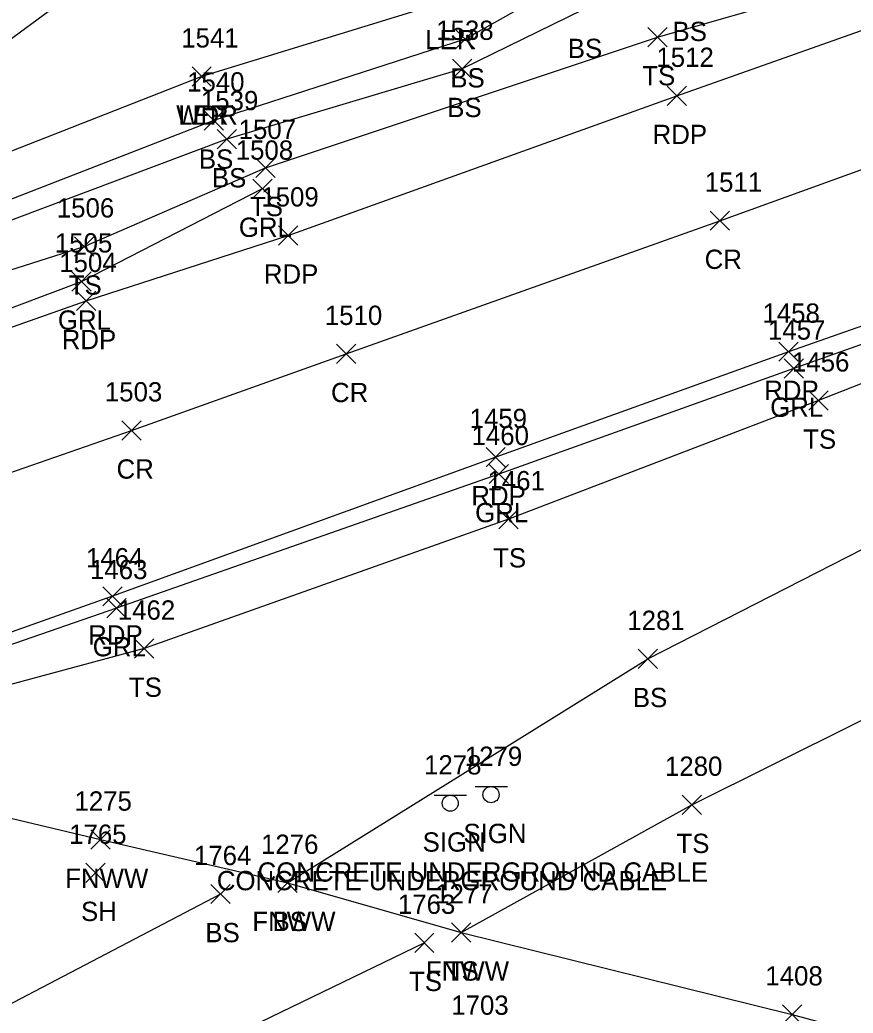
# Model space of a CAD drawing. Extents: x 1599569 to 1610055, y 642560 to 647860.
# Drawn here: x 1601829.7 to 1601916, y 647289.9 to 647392.8 of the extents above; entities that cross this region are included whole.
import ezdxf

# ---------------------------------------------------------------- set-up
doc = ezdxf.new("R2010")
doc.units = 0
for name, color, linetype in [('L_A', 7, 'Continuous'), ('L_I', 7, 'Continuous'), ('L_TIC', 7, 'Continuous'), ('LARO', 7, 'Continuous'), ('LAWA', 7, 'Continuous'), ('LELB', 7, 'Continuous'), ('LFNC', 7, 'Continuous'), ('P_A', 7, 'Continuous'), ('P_I', 7, 'Continuous'), ('P_TIC', 7, 'Continuous'), ('PET', 7, 'Continuous'), ('PRC', 7, 'Continuous'), ('R_A', 7, 'Continuous'), ('R_I', 7, 'Continuous'), ('R_TIC', 7, 'Continuous'), ('RGR', 7, 'Continuous'), ('S_A', 7, 'Continuous'), ('S_C', 7, 'Continuous'), ('S_I', 7, 'Continuous'), ('SSGN', 7, 'Continuous')]:
    doc.layers.add(name, color=color, linetype=linetype)

msp = doc.modelspace()

# ---------------------------------------------------------------- linework, layer by layer
at = {"layer": 'L_TIC'}
for points in [[(1601894.73, 647390.04), (1601896.73, 647392.04)], [(1601896.73, 647390.04), (1601894.73, 647392.04)], [(1601874.8, 647389.82), (1601876.8, 647391.82)], [(1601876.8, 647389.82), (1601874.8, 647391.82)], [(1601847.49, 647385.96), (1601849.49, 647387.96)], [(1601849.49, 647385.96), (1601847.49, 647387.96)], [(1601847.49, 647385.96), (1601849.49, 647387.96)], [(1601849.49, 647385.96), (1601847.49, 647387.96)], [(1601874.49, 647386.75), (1601876.49, 647388.75)], [(1601876.49, 647386.75), (1601874.49, 647388.75)], [(1601848.76, 647381.4), (1601850.76, 647383.4)], [(1601850.76, 647381.4), (1601848.76, 647383.4)], [(1601850.11, 647379.46), (1601852.11, 647381.46)], [(1601852.11, 647379.46), (1601850.11, 647381.46)], [(1601854.09, 647376.48), (1601856.09, 647378.48)], [(1601856.09, 647376.48), (1601854.09, 647378.48)], [(1601835.31, 647368.34), (1601837.31, 647370.34)], [(1601837.31, 647368.34), (1601835.31, 647370.34)], [(1601911.4, 647352.37), (1601913.4, 647354.37)], [(1601913.4, 647352.37), (1601911.4, 647354.37)], [(1601879.28, 647340.06), (1601881.28, 647342.06)], [(1601881.28, 647340.06), (1601879.28, 647342.06)], [(1601841.54, 647326.65), (1601843.54, 647328.65)], [(1601843.54, 647326.65), (1601841.54, 647328.65)], [(1601893.72, 647325.58), (1601895.72, 647327.58)], [(1601895.72, 647325.58), (1601893.72, 647327.58)], [(1601898.27, 647310.46), (1601900.27, 647312.46)], [(1601900.27, 647310.46), (1601898.27, 647312.46)], [(1601837.01, 647306.85), (1601839.01, 647308.85)], [(1601839.01, 647306.85), (1601837.01, 647308.85)], [(1601836.5, 647303.41), (1601838.5, 647305.41)], [(1601838.5, 647303.41), (1601836.5, 647305.41)], [(1601856.39, 647302.37), (1601858.39, 647304.37)], [(1601858.39, 647302.37), (1601856.39, 647304.37)], [(1601856.39, 647302.37), (1601858.39, 647304.37)], [(1601858.39, 647302.37), (1601856.39, 647304.37)], [(1601849.43, 647301.21), (1601851.43, 647303.21)], [(1601851.43, 647301.21), (1601849.43, 647303.21)], [(1601874.37, 647297.23), (1601876.37, 647299.23)], [(1601876.37, 647297.23), (1601874.37, 647299.23)], [(1601874.37, 647297.23), (1601876.37, 647299.23)], [(1601876.37, 647297.23), (1601874.37, 647299.23)], [(1601870.56, 647296.15), (1601872.56, 647298.15)], [(1601872.56, 647296.15), (1601870.56, 647298.15)], [(1601908.67, 647288.73), (1601910.67, 647290.73)], [(1601910.67, 647288.73), (1601908.67, 647290.73)]]:
    msp.add_lwpolyline(points, dxfattribs=at)
at = {"layer": 'LARO'}
msp.add_lwpolyline([(1602281.17, 647528.1), (1602249.28, 647518.68), (1602215.29, 647506.81), (1602182.96, 647503.09), (1602138.81, 647485.94), (1602110.91, 647474.13), (1602102.89, 647472.66), (1602065.84, 647459), (1602030.57, 647446.06), (1601996.63, 647434.93), (1601966.44, 647449.06), (1601954.75, 647432.61), (1601939.14, 647421.32), (1601907.5, 647403.47), (1601898.14, 647399.78), (1601888.11, 647399.67), (1601874.07, 647394.79), (1601848.49, 647386.96)], dxfattribs=at)
at = {"layer": 'LAWA'}
msp.add_lwpolyline([(1601848.49, 647386.96), (1601821.55, 647376.37), (1601804, 647372.6), (1601777.94, 647362.34), (1601760.01, 647349.17), (1601740.19, 647347.52), (1601705.98, 647345.02), (1601664.4, 647344.49), (1601627.88, 647353.13)], dxfattribs=at)
at = {"layer": 'LELB'}
for points in [[(1602281.75, 647527.04), (1602249.8, 647516.84), (1602215.67, 647505.92), (1602184.38, 647497.32), (1602140.31, 647484.48), (1602111.03, 647472.46), (1602103.56, 647472.02), (1602066.93, 647456.96), (1602030.71, 647444.95), (1601997.32, 647432.85), (1601974.14, 647429.14), (1601941.15, 647416.78), (1601908.35, 647402.2), (1601898.71, 647398.5), (1601889.19, 647398.4), (1601875.8, 647390.82), (1601849.76, 647382.4), (1601821.01, 647371.25), (1601793.34, 647364.77), (1601777.94, 647362.34), (1601752.2, 647359.53), (1601736.48, 647357.95), (1601705.98, 647345.02)], [(1602280.55, 647523.47), (1602249.62, 647512.84), (1602216.53, 647503.11), (1602185.17, 647491.71), (1602142.18, 647479.3), (1602111.48, 647470.2), (1602106.19, 647468.46), (1602102.05, 647467.18), (1602101.62, 647468.1), (1602067.36, 647454.23), (1602033.18, 647442.57), (1601998.29, 647429.71), (1601975.48, 647422.42), (1601942.86, 647410.81), (1601909.09, 647400.02), (1601898.83, 647395.63), (1601887.98, 647393.87), (1601875.49, 647387.75), (1601851.11, 647380.46), (1601821.5, 647369.32), (1601787.55, 647360.24), (1601760.01, 647349.17)], [(1601875.37, 647298.23), (1601899.27, 647311.46), (1601933.4, 647328.44), (1601966.96, 647349.6), (1601991.6, 647361.72), (1602007.33, 647369.55), (1602053.05, 647388.73), (1602108.48, 647405.48), (1602138.7, 647415.54), (1602162.27, 647422.58), (1602191.63, 647430.16), (1602222.72, 647436.69), (1602253.77, 647437.09), (1602274.71, 647434), (1602308.64, 647432.46), (1602335.54, 647436.29), (1602372.31, 647451.76), (1602413.17, 647464.59), (1602450.85, 647476.95), (1602485.79, 647485.59)], [(1602272.83, 647479.89), (1602236.83, 647468.86), (1602208.71, 647455.65), (1602173.71, 647445.42), (1602136.85, 647432.86), (1602103.5, 647421.49), (1602068.54, 647408.84), (1602020.23, 647391.97), (1601979.79, 647378.49), (1601945.53, 647366.37), (1601912.4, 647353.37), (1601880.28, 647341.06), (1601842.54, 647327.65), (1601807.18, 647318.11)], [(1601770.52, 647348.15), (1601798.65, 647357.36), (1601836.31, 647369.34), (1601855.09, 647377.48), (1601895.73, 647391.04), (1601936.03, 647402.6), (1601976.97, 647416.76)], [(1601850.43, 647302.21), (1601817.07, 647284.74), (1601803.58, 647280.33), (1601784.13, 647281.69), (1601758.75, 647290.86), (1601723.07, 647307), (1601685.47, 647323.96), (1601675.62, 647324.78), (1601658.01, 647334.35), (1601634.9, 647343.88), (1601612.64, 647349.36), (1601572.76, 647365.6), (1601544.62, 647379.24), (1601520.15, 647401.41)], [(1601857.39, 647303.37), (1601894.72, 647326.58), (1601931.36, 647345.31), (1601962.26, 647363.09), (1601988.12, 647373.2), (1602026.56, 647383.89)], [(1601871.56, 647297.15), (1601825.85, 647275.03), (1601803.11, 647261.21)]]:
    msp.add_lwpolyline(points, dxfattribs=at)
at = {"layer": 'LFNC'}
for points in [[(1601895.17, 647441.71), (1601881.57, 647431.46), (1601862.81, 647416.78), (1601844.07, 647402.17), (1601817.02, 647382.22)], [(1601805.75, 647315.97), (1601814.87, 647313.37), (1601838.01, 647307.85), (1601857.39, 647303.37), (1601875.37, 647298.23), (1601909.67, 647289.73), (1601944.01, 647280.41), (1601968.24, 647274.13), (1601982.37, 647269.76), (1602013.8, 647257.69), (1602065.95, 647235.95), (1602107.23, 647215.87), (1602133.46, 647203.49), (1602174.23, 647185.03), (1602218.38, 647164.67)]]:
    msp.add_lwpolyline(points, dxfattribs=at)
at = {"layer": 'P_TIC'}
for points in [[(1601896.73, 647383.95), (1601898.73, 647385.95)], [(1601898.73, 647383.95), (1601896.73, 647385.95)], [(1601901.17, 647371.01), (1601903.17, 647373.01)], [(1601903.17, 647371.01), (1601901.17, 647373.01)], [(1601856.45, 647369.48), (1601858.45, 647371.48)], [(1601858.45, 647369.48), (1601856.45, 647371.48)], [(1601835.51, 647362.69), (1601837.51, 647364.69)], [(1601837.51, 647362.69), (1601835.51, 647364.69)], [(1601862.46, 647357.2), (1601864.46, 647359.2)], [(1601864.46, 647357.2), (1601862.46, 647359.2)], [(1601908.28, 647357.43), (1601910.28, 647359.43)], [(1601910.28, 647357.43), (1601908.28, 647359.43)], [(1601840.23, 647349.27), (1601842.23, 647351.27)], [(1601842.23, 647349.27), (1601840.23, 647351.27)], [(1601877.95, 647346.51), (1601879.95, 647348.51)], [(1601879.95, 647346.51), (1601877.95, 647348.51)], [(1601838.24, 647332.07), (1601840.24, 647334.07)], [(1601840.24, 647332.07), (1601838.24, 647334.07)]]:
    msp.add_lwpolyline(points, dxfattribs=at)
at = {"layer": 'PET'}
msp.add_lwpolyline([(1601944.09, 647370.64), (1601909.28, 647358.43), (1601878.95, 647347.51), (1601839.24, 647333.07), (1601805.32, 647321.01), (1601803.15, 647319.96), (1601792.41, 647316.42), (1601770.61, 647326.17), (1601751.67, 647334.63), (1601759.02, 647336.99), (1601802.16, 647351.59), (1601836.51, 647363.69), (1601857.45, 647370.48), (1601897.73, 647384.95), (1601937.45, 647399.06)], dxfattribs=at)
at = {"layer": 'PRC'}
msp.add_lwpolyline([(1601770.61, 647326.17), (1601806.22, 647338.1), (1601841.23, 647350.27), (1601863.46, 647358.2), (1601902.17, 647372.01), (1601941.02, 647386.06), (1601983.17, 647400.81)], dxfattribs=at)
at = {"layer": 'R_TIC'}
for points in [[(1601853.79, 647374.33), (1601855.79, 647376.33)], [(1601855.79, 647374.33), (1601853.79, 647376.33)], [(1601835.05, 647364.71), (1601837.05, 647366.71)], [(1601837.05, 647364.71), (1601835.05, 647366.71)], [(1601908.85, 647355.68), (1601910.85, 647357.68)], [(1601910.85, 647355.68), (1601908.85, 647357.68)], [(1601878.27, 647344.75), (1601880.27, 647346.75)], [(1601880.27, 647344.75), (1601878.27, 647346.75)], [(1601838.66, 647330.85), (1601840.66, 647332.85)], [(1601840.66, 647330.85), (1601838.66, 647332.85)]]:
    msp.add_lwpolyline(points, dxfattribs=at)
at = {"layer": 'RGR'}
for points in [[(1602208.13, 647459.7), (1602171.04, 647448.96), (1602135.43, 647436.66), (1602102.2, 647424.86), (1602066.88, 647412.28), (1602018.59, 647395.18), (1601979.38, 647381.34), (1601944.8, 647369.09), (1601909.85, 647356.68), (1601879.27, 647345.75), (1601839.66, 647331.85), (1601805.55, 647320.04)], [(1601760.15, 647338.14), (1601801.96, 647352.88), (1601836.05, 647365.71), (1601854.79, 647375.33)]]:
    msp.add_lwpolyline(points, dxfattribs=at)
at = {"layer": 'SSGN'}
for p, q in [((1601876.82, 647313.34), (1601880.16, 647313.34)), ((1601872.59, 647312.45), (1601875.93, 647312.45)), ((1601878.47, 647312.51), (1601878.47, 647312.51)), ((1601874.24, 647311.62), (1601874.24, 647311.62))]:
    msp.add_line(p, q, dxfattribs=at)
for centre in [(1601878.47, 647312.51), (1601874.24, 647311.62)]:
    msp.add_circle(centre, 0.833, dxfattribs=at)

# ---------------------------------------------------------------- texts
at = {"layer": 'L_A'}
for s, p in [('BS', (1601897.27, 647390.63)), ('LER', (1601871.65, 647389.79)), ('BS', (1601886.42, 647388.87)), ('TS', (1601894.14, 647386.04)), ('BS', (1601874.25, 647385.82)), ('WDR', (1601845.85, 647381.96)), ('LER', (1601846.07, 647381.96)), ('BS', (1601873.93, 647382.75)), ('BS', (1601848.2, 647377.4)), ('BS', (1601849.55, 647375.46)), ('TS', (1601853.5, 647372.48)), ('TS', (1601834.72, 647364.34)), ('TS', (1601910.81, 647348.37)), ('TS', (1601878.69, 647336.06)), ('TS', (1601840.95, 647322.65)), ('BS', (1601893.16, 647321.58)), ('TS', (1601897.68, 647306.46)), ('FNWW', (1601834.35, 647302.85)), ('SH', (1601835.99, 647299.41)), ('FNWW', (1601853.74, 647298.37)), ('BS', (1601855.83, 647298.37)), ('BS', (1601848.87, 647297.21)), ('FNWW', (1601871.72, 647293.23)), ('TS', (1601873.78, 647293.23)), ('TS', (1601869.97, 647292.15))]:
    msp.add_text(s, height=2, dxfattribs=at).set_placement(p)
at = {"layer": 'L_I'}
for s, p in [('1538', (1601872.79, 647390.75)), ('1541', (1601846.37, 647389.96)), ('1541', (1601846.37, 647389.96)), ('1540', (1601846.98, 647385.4)), ('1539', (1601848.41, 647383.46)), ('1507', (1601852.32, 647380.48)), ('1506', (1601833.48, 647372.34)), ('1456', (1601909.65, 647356.37)), ('1461', (1601878.1, 647344.06)), ('1462', (1601839.8, 647330.65)), ('1281', (1601892.59, 647329.58)), ('1280', (1601896.49, 647314.46)), ('1275', (1601835.31, 647310.85)), ('1765', (1601834.76, 647307.41)), ('1276', (1601854.64, 647306.37)), ('1276', (1601854.64, 647306.37)), ('1764', (1601847.69, 647305.21)), ('1277', (1601872.68, 647301.23)), ('1277', (1601872.68, 647301.23)), ('1763', (1601868.82, 647300.15)), ('1408', (1601906.89, 647292.73)), ('1703', (1601874.35, 647289.69))]:
    msp.add_text(s, height=2, dxfattribs=at).set_placement(p)
at = {"layer": 'P_A'}
for s, p in [('RDP', (1601895.21, 647379.95)), ('CR', (1601900.6, 647367.01)), ('RDP', (1601854.93, 647365.48)), ('RDP', (1601833.99, 647358.69)), ('CR', (1601861.89, 647353.2)), ('RDP', (1601906.77, 647353.43)), ('CR', (1601839.67, 647345.27)), ('RDP', (1601876.43, 647342.51)), ('RDP', (1601836.73, 647328.07))]:
    msp.add_text(s, height=2, dxfattribs=at).set_placement(p)
at = {"layer": 'P_I'}
for s, p in [('1512', (1601895.6, 647387.95)), ('1511', (1601900.61, 647375.01)), ('1509', (1601854.67, 647373.48)), ('1504', (1601833.73, 647366.69)), ('1510', (1601861.25, 647361.2)), ('1458', (1601906.59, 647361.43)), ('1503', (1601838.46, 647353.27)), ('1459', (1601876.25, 647350.51)), ('1464', (1601836.5, 647336.07))]:
    msp.add_text(s, height=2, dxfattribs=at).set_placement(p)
at = {"layer": 'R_A'}
for p in [(1601852.34, 647370.33), (1601833.59, 647360.71), (1601907.39, 647351.68), (1601876.82, 647340.75), (1601837.2, 647326.85)]:
    msp.add_text('GRL', height=2, dxfattribs=at).set_placement(p)
at = {"layer": 'R_I'}
for s, p in [('1508', (1601852.02, 647378.33)), ('1505', (1601833.28, 647368.71)), ('1457', (1601907.16, 647359.68)), ('1460', (1601876.45, 647348.75)), ('1463', (1601836.92, 647334.85))]:
    msp.add_text(s, height=2, dxfattribs=at).set_placement(p)
at = {"layer": 'S_A'}
for p in [(1601871.38, 647306.6), (1601875.61, 647307.49)]:
    msp.add_text('SIGN', height=2, dxfattribs=at).set_placement(p)
at = {"layer": 'S_C'}
for p in [(1601854.29, 647303.49), (1601850.06, 647302.6)]:
    msp.add_text('CONCRETE UNDERGROUND CABLE', height=2, dxfattribs=at).set_placement(p)
at = {"layer": 'S_I'}
for s, p in [('1279', (1601875.75, 647315.49)), ('1278', (1601871.53, 647314.6))]:
    msp.add_text(s, height=2, dxfattribs=at).set_placement(p)

doc.saveas('drawing.dxf')
